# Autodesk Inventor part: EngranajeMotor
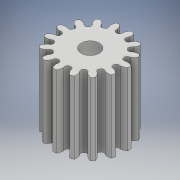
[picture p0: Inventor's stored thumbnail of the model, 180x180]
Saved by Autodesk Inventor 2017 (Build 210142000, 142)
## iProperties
Created: 2019-07
Part Number: EngranajeMotor
Material: Genérico
Document SubType Name: Modeling
Designer: Diego
Density: 1 g/cm^3
Appearance: Valor por defecto
Title: C:/Users/Diego/Downloads/9/Animalitos/Engranaje.step
Sending System: Autodesk Translation Framework v8.2.0.1029
Preprocessor: ST-DEVELOPER v18
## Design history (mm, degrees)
feature "Body1"
node "Sólido1"
